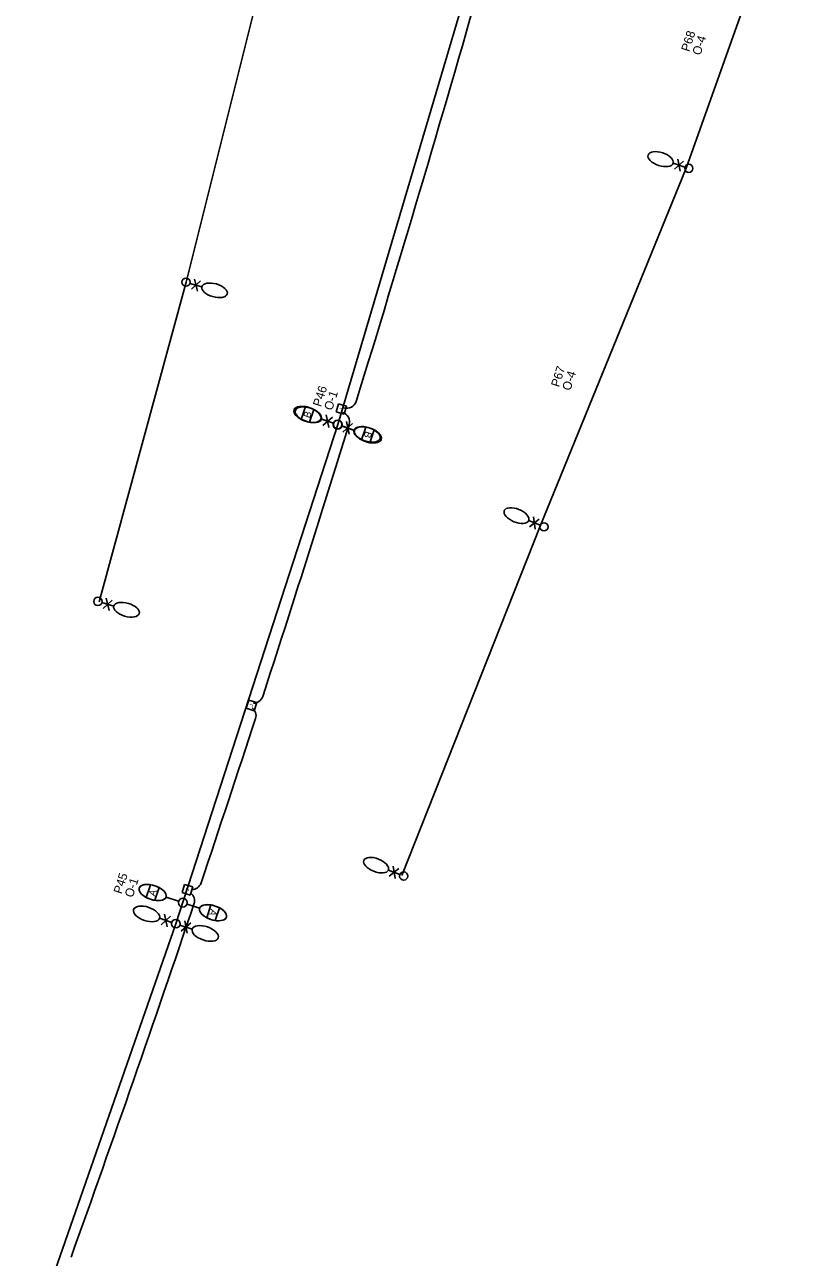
# Model space of a CAD drawing. Extents: x 925407 to 930994, y 604905 to 637063.
# Drawn here: x 930041 to 930485, y 616694 to 617398 of the extents above; entities that cross this region are included whole.
import ezdxf

# ---------------------------------------------------------------- set-up
doc = ezdxf.new("R2010")
doc.units = 0
for name, color, linetype in [('ActivePointCell_dp', 7, 'Continuous'), ('ConduitOT', 7, 'Continuous'), ('LiteCond_ep', 7, 'Continuous'), ('Miscellaneous2', 7, 'Continuous'), ('Miscellaneous9', 7, 'Continuous'), ('PoleLight', 7, 'Continuous'), ('PoleLight_ep', 7, 'Continuous'), ('PullBox', 7, 'Continuous')]:
    doc.layers.add(name, color=color, linetype=linetype)

msp = doc.modelspace()

# ---------------------------------------------------------------- linework, layer by layer
at = {"layer": 'ConduitOT'}
for centre, radius, start, end in [((919241.37, 620573.8), 11500, 342.850133, 344.101079), ((930224.7, 617184.37), 5.5, 252.60703, 343.37421), ((930220.72, 617171.23), 5.5, 342.93802, 73.7052), ((919241.37, 620573.8), 11500, 341.969976, 342.782936), ((930171.45, 617016.12), 5.5, 270.04974, 341.42043), ((930167.36, 617003.58), 5.5, 342.40213, 53.77282), ((919241.37, 620573.8), 11500, 341.411751, 341.904717), ((930136.25, 616909.75), 5.5, 270.04974, 341.42043), ((930132.25, 616897.88), 5.5, 341.35798, 52.43785), ((919241.37, 620573.8), 11500, 340.284973, 341.350681)]:
    msp.add_arc(centre, radius, start, end, dxfattribs=at)
at = {"layer": 'LiteCond_ep'}
for p, q in [((930418.32, 617315.83), (930485.3, 617503.97)), ((930132.91, 617250.83), (930180.76, 617442.27)), ((930219.49, 617169.61), (930298.83, 617437.02)), ((930335.05, 617111.54), (930418.32, 617315.83)), ((930083.34, 617068.51), (930132.91, 617250.83)), ((930127.1, 616884.67), (930219.49, 617169.61)), ((930256.02, 616912.17), (930335.05, 617111.54)), ((930040.78, 616637.4), (930127.1, 616884.67))]:
    msp.add_line(p, q, dxfattribs=at)
at = {"layer": 'Miscellaneous2'}
for p, q in [((930201.07, 617179.81), (930198.61, 617172.55)), ((930201.07, 617179.81), (930201.07, 617179.81)), ((930203.44, 617170.91), (930205.9, 617178.17)), ((930205.9, 617178.17), (930205.9, 617178.17)), ((930235.5, 617168.15), (930233.04, 617160.88)), ((930235.5, 617168.15), (930235.5, 617168.15)), ((930237.87, 617159.25), (930240.33, 617166.51)), ((930240.33, 617166.51), (930240.33, 617166.51)), ((930112.65, 616906.97), (930110.22, 616899.7)), ((930112.65, 616906.97), (930112.65, 616906.97)), ((930115.05, 616898.09), (930117.49, 616905.36)), ((930117.49, 616905.36), (930117.49, 616905.36)), ((930147.13, 616895.45), (930144.69, 616888.18)), ((930147.13, 616895.45), (930147.13, 616895.45)), ((930149.53, 616886.56), (930151.96, 616893.83)), ((930151.96, 616893.83), (930151.96, 616893.83))]:
    msp.add_line(p, q, dxfattribs=at)
for centre, major_axis, start_param, end_param in [((930202.25, 617175.36), (7.65, -2.59), 1.249648, 1.891946), ((930202.25, 617175.36), (7.65, -2.59), 4.391241, 4.391271), ((930202.25, 617175.36), (7.65, -2.59), 4.391271, 5.033538), ((930236.68, 617163.7), (7.65, -2.59), 1.249648, 1.891946), ((930236.68, 617163.7), (7.65, -2.59), 4.391241, 4.391271), ((930236.68, 617163.7), (7.65, -2.59), 4.391271, 5.033538), ((930113.85, 616902.53), (7.66, -2.56), 1.249648, 1.891946), ((930113.85, 616902.53), (7.66, -2.56), 4.391241, 4.391271), ((930113.85, 616902.53), (7.66, -2.56), 4.391271, 5.033538), ((930148.33, 616891), (7.66, -2.56), 1.249648, 1.891946), ((930148.33, 616891), (7.66, -2.56), 4.391241, 4.391271), ((930148.33, 616891), (7.66, -2.56), 4.391271, 5.033538)]:
    msp.add_ellipse(centre, major_axis=major_axis, ratio=0.5, start_param=start_param, end_param=end_param, dxfattribs=at)
at = {"layer": 'PoleLight'}
for p, q in [((930198.61, 617172.55), (930201.07, 617179.81)), ((930205.9, 617178.17), (930203.44, 617170.91)), ((930217.08, 617170.34), (930209.9, 617172.77)), ((930221.86, 617168.72), (930229.03, 617166.29)), ((930233.04, 617160.88), (930235.5, 617168.15)), ((930240.33, 617166.51), (930237.87, 617159.25)), ((930110.22, 616899.7), (930112.65, 616906.97)), ((930117.49, 616905.36), (930115.05, 616898.09)), ((930128.7, 616897.57), (930121.51, 616899.97)), ((930133.48, 616895.97), (930140.67, 616893.56)), ((930144.69, 616888.18), (930147.13, 616895.45)), ((930151.96, 616893.83), (930149.53, 616886.56))]:
    msp.add_line(p, q, dxfattribs=at)
for centre in [(930219.47, 617169.53), (930219.47, 617169.53), (930131.09, 616896.77), (930131.09, 616896.77)]:
    msp.add_circle(centre, 2.52, dxfattribs=at)
for centre, major_axis in [((930202.25, 617175.36), (7.65, -2.59)), ((930236.68, 617163.7), (7.65, -2.59)), ((930113.85, 616902.53), (7.66, -2.56)), ((930148.33, 616891), (7.66, -2.56))]:
    msp.add_ellipse(centre, major_axis=major_axis, ratio=0.5, dxfattribs=at)
for centre, major_axis, start_param, end_param in [((930202.25, 617175.36), (7.65, -2.59), 1.891945, 4.391241), ((930202.25, 617175.36), (7.65, -2.59), 5.033538, 6.283185), ((930202.25, 617175.36), (7.65, -2.59), 0.847605, 1.249648), ((930202.25, 617175.36), (7.65, -2.59), 0, 0.847605), ((930236.68, 617163.7), (7.65, -2.59), 1.891945, 4.391241), ((930236.68, 617163.7), (7.65, -2.59), 0.847605, 1.249648), ((930236.68, 617163.7), (7.65, -2.59), 0, 0.847605), ((930236.68, 617163.7), (7.65, -2.59), 5.033538, 6.283185), ((930113.85, 616902.53), (7.66, -2.56), 1.891945, 4.391241), ((930113.85, 616902.53), (7.66, -2.56), 0.847605, 1.249648), ((930113.85, 616902.53), (7.66, -2.56), 5.033538, 6.283185), ((930113.85, 616902.53), (7.66, -2.56), 0, 0.847605), ((930148.33, 616891), (7.66, -2.56), 1.891945, 4.391241), ((930148.33, 616891), (7.66, -2.56), 0.847605, 1.249648), ((930148.33, 616891), (7.66, -2.56), 0, 0.847605), ((930148.33, 616891), (7.66, -2.56), 5.033538, 6.283185)]:
    msp.add_ellipse(centre, major_axis=major_axis, ratio=0.5, start_param=start_param, end_param=end_param, dxfattribs=at)
at = {"layer": 'PoleLight_ep'}
for p, q in [((930411.7, 617315.27), (930416.95, 617319.99)), ((930413.6, 617321.08), (930415.06, 617314.18)), ((930417.68, 617316.53), (930410.97, 617318.73)), ((930135.17, 617250.18), (930141.96, 617248.25)), ((930141.1, 617251.68), (930136.03, 617246.76)), ((930139.43, 617245.8), (930137.7, 617252.64)), ((930217.16, 617170.35), (930210.18, 617172.67)), ((930210.98, 617169.01), (930216.48, 617173.89)), ((930212.99, 617175.05), (930214.47, 617167.85)), ((930221.81, 617168.8), (930228.78, 617166.48)), ((930227.99, 617170.14), (930222.49, 617165.26)), ((930225.97, 617164.1), (930224.5, 617171.3)), ((930328.99, 617111.29), (930334.57, 617115.61)), ((930331.3, 617116.95), (930332.26, 617109.95)), ((930335.05, 617112.12), (930328.51, 617114.78)), ((930084.84, 617068), (930091.66, 617066.01)), ((930090.82, 617069.46), (930085.69, 617064.55)), ((930089.1, 617063.56), (930087.41, 617070.45)), ((930254.99, 616912.78), (930248.42, 616915.37)), ((930248.94, 616911.88), (930254.47, 616916.27)), ((930251.19, 616917.57), (930252.23, 616910.59)), ((930120.63, 616890.22), (930122.1, 616883.02)), ((930124.8, 616885.52), (930117.82, 616887.85)), ((930118.62, 616884.18), (930124.12, 616889.06)), ((930129.45, 616883.97), (930136.42, 616881.65)), ((930135.62, 616885.31), (930130.13, 616880.44)), ((930133.61, 616879.27), (930132.14, 616886.47))]:
    msp.add_line(p, q, dxfattribs=at)
for centre, radius in [((930419.92, 617315.8), 2.35), ((930132.91, 617250.83), 2.35), ((930219.48, 617169.57), 2.45), ((930337.22, 617111.23), 2.35), ((930082.57, 617068.66), 2.37), ((930257.18, 616911.92), 2.35), ((930127.12, 616884.75), 2.45)]:
    msp.add_circle(centre, radius, dxfattribs=at)
for centre, major_axis in [((930403.82, 617321.06), (-7.16, 2.34)), ((930149.2, 617246.2), (7.24, -2.06)), ((930202.75, 617175.15), (-7.44, 2.48)), ((930236.22, 617164), (7.44, -2.48)), ((930321.54, 617117.63), (-6.97, 2.84)), ((930098.93, 617063.9), (7.27, -2.12)), ((930241.42, 616918.14), (-7, 2.76)), ((930110.38, 616890.32), (-7.44, 2.48)), ((930143.86, 616879.17), (7.44, -2.48))]:
    msp.add_ellipse(centre, major_axis=major_axis, ratio=0.5, dxfattribs=at)
at = {"layer": 'PullBox'}
for p, q in [((930218.54, 617176.83), (930219.95, 617181.47)), ((930219.95, 617181.47), (930224.58, 617180.06)), ((930224.58, 617180.06), (930223.18, 617175.43)), ((930223.18, 617175.43), (930218.54, 617176.83)), ((930167.19, 617007.77), (930168.68, 617012.38)), ((930168.68, 617012.38), (930173.29, 617010.89)), ((930173.29, 617010.89), (930171.8, 617006.28)), ((930171.8, 617006.28), (930167.19, 617007.77)), ((930130.62, 616902.57), (930132.11, 616907.18)), ((930132.11, 616907.18), (930136.72, 616905.69)), ((930136.72, 616905.69), (930135.23, 616901.08)), ((930135.23, 616901.08), (930130.62, 616902.57))]:
    msp.add_line(p, q, dxfattribs=at)

# ---------------------------------------------------------------- texts
at = {"layer": 'ActivePointCell_dp'}
for s, p in [('P68', (930420.14, 617382.02)), ('O-4', (930426.52, 617379.97)), ('P67', (930345.85, 617190.63)), ('O-4', (930352.23, 617188.59)), ('P46', (930209.92, 617179.39)), ('O-1', (930216.3, 617177.34)), ('P45', (930096.11, 616901.39)), ('O-1', (930102.49, 616899.35))]:
    msp.add_text(s, height=5, rotation=72.21332, dxfattribs=at).set_placement(p)
at = {"layer": 'Miscellaneous9'}
for s, rotation, p in [('B', 71.29, (930203.59, 617172.94)), ('B', 251.29, (930235.35, 617166.12)), ('A', 71.51419, (930115.18, 616900.08)), ('A', 251.51419, (930147, 616893.45))]:
    msp.add_text(s, height=4.08, rotation=rotation, dxfattribs=at).set_placement(p)
at = {"layer": 'PullBox'}
for rotation, p in [(73.15611, (930222.3, 617177.54)), (72.10457, (930170.96, 617008.41)), (72.10457, (930134.39, 616903.21))]:
    msp.add_text('J', height=1.94, rotation=rotation, dxfattribs=at).set_placement(p)

doc.saveas('drawing.dxf')
